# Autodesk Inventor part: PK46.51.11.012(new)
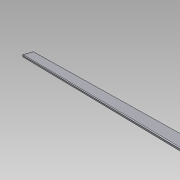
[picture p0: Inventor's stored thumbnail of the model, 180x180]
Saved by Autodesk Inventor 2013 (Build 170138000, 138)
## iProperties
Created: 2005-11
Part Number: PK46.51.11.012(new)
Material: Steel, Mild
Document SubType Name: Листовой материал
Designer: =<Author>
Manufacturer: Standard
Standards Organization: Custom
Density: 7.86 g/cm^3
Flat Pattern Width: 7.05239 cm
Flat Pattern Length: 95.8044 cm
Flat Pattern Area: 675.65 cm^2
Sheet Metal Rule: По умолчанию
Description: =<Part Number>
Mass: 1052.89 g
Surface Area: 1380.31 cm^2
Volume: 133.956 cm^3
Толщина: 2.000 mm
Радиус_гибки: 2.000 mm
Ширина_просечки: 2.000 mm
Глубина_просечки: 1.000 mm
Размер_высечки: 8.000 mm
Минимальный_остаток: 4.000 mm
Радиус_перехода: 2.000 mm
JacobiRadiusSize: 2.000 mm
GapSize: 2.000 mm
d0: 933.000 mm
d1: 62.000 mm
d3: 80.07 deg
d4: 2.000 mm
d5: 2.000 mm
d6: 1.000 mm
d7: 4.000 mm
d8: 2.000 mm
d9: 10.000 mm
d10: 90.00 deg
d11: 2.000 mm
Author: PVitaliy
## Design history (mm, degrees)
node "Грань1"
node "Фланец1"
body "Solid1"
sketch "Эскиз2"
  geometry: L1 (0, 0)-(947.19, 0); L2 (947.19, 0)-(958.044, 62); L3 (958.044, 62)-(10.854, 62); L4 (10.854, 62)-(0, 0)
  constraints: 8 end point, 2 horizontal, 1 parallel, 1 other
  dimensions: "d0" = 933 distance between parallel lines of L2 L4; "d1" = 62 distance between parallel lines of L3 L1; "d3" = 80.07 deg angle of L4 L1
feature "Плакирование1" dims "Толщина" = 2
sketch "Эскиз3"
  geometry: L1 through (-473.595, 0) direction (-1, 0); L2 (-947.19, 0)-(-947.19, -10); L3 (-947.19, -10)-(0, -10); L4 through (0, -5) direction (0, 1)
  constraints: 6 end point, 1 horizontal, 1 perpendicular, 1 vertical
feature "Плакирование2" dims "d5" = 2 (= Ширина_просечки), "d7" = 4 (= Минимальный_остаток), "d9" = 10, angle "d10" = 90 deg, "d11" = 2 (= Радиус_гибки), "Толщина" = 2
feature "Изгиб1" dims "d5" = 2 (= Ширина_просечки), "d6" = 1 (= Глубина_просечки), "d7" = 4 (= Минимальный_остаток), "d8" = 2 (= Радиус_гибки), "d9" = 10, angle "d10" = 90 deg, "d11" = 2 (= Радиус_гибки), "Толщина" = 2, "Зазор_стыка" = 0.01
node "Развертка"
feature "FlatPatternExtrusion2" dims "d0" = 2 (derived)
other parameters: "Радиус_гибки" = 2 (= Толщина), "Ширина_просечки" = 2 (= Толщина), "Глубина_просечки" = 1 (= 0.5 x Толщина), "Размер_высечки" = 8 (= 4 x Толщина), "Минимальный_остаток" = 4 (= 2 x Толщина), "Радиус_перехода" = 2 (= Радиус_гибки), "d4" = 2 (= Радиус_гибки), "JacobiRadiusSize" = 2 (= Толщина), "GapSize" = 2 (= Толщина)
